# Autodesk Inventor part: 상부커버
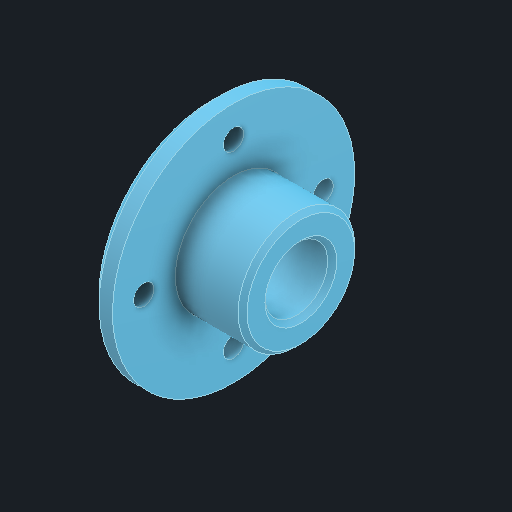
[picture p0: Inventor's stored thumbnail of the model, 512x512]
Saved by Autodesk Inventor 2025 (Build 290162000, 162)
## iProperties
Created: 2025-08
Part Number: 상부커버
Material: 알루미늄 6061
Document SubType Name: Modeling
Designer: infra023
Density: 2.71 g/cm^3
Appearance: 기본값
Author: jhkim
Sending System: Autodesk Inventor 2026
Preprocessor: ST-DEVELOPER v20.1
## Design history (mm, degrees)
feature "솔리드1"
node "솔리드2"
